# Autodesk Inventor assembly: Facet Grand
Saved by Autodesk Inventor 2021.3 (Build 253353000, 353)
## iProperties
Created: 2022-09
Part Number: Facet Grand
Document SubType Name: Assembly
Designer: Administrator
Title: Facet Grand v7
Author: Administrator
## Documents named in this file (3)
- c:\worker\convert-fusion-r05\tmp\job-1\2479\output\files\a20e6ee4-7efd-4201-9475-8a9acd1a8a35\9d3c9cd0-538a-4c76-b8b2-125934039231.iam
- c:\worker\convert-fusion-r05\tmp\job-1\2479\output\files\a20e6ee4-7efd-4201-9475-8a9acd1a8a35\Facet Grand.ipt
- c:\worker\convert-fusion-r05\tmp\job-1\2479\output\files\a20e6ee4-7efd-4201-9475-8a9acd1a8a35\Part4.ipt
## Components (2 placed, 2 different names)
1. Facet Grand:1
2. Part4
